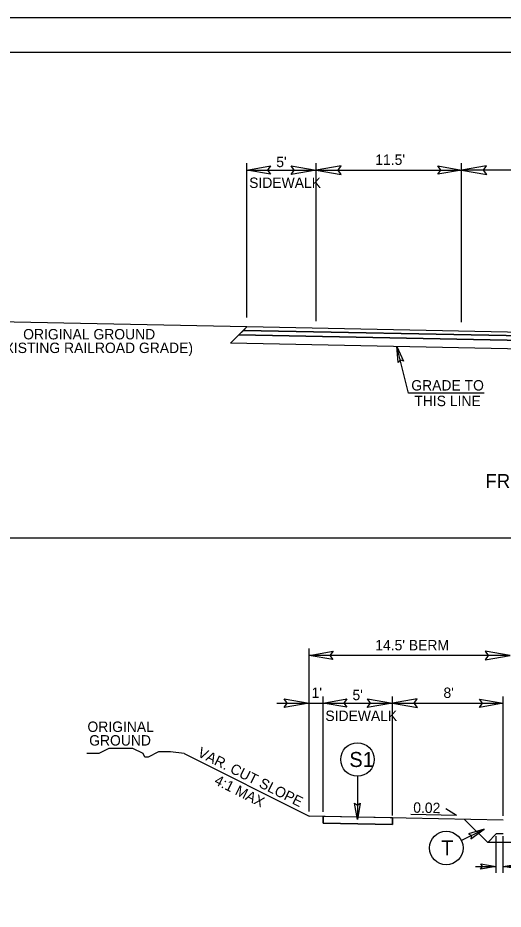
# Model space of a CAD drawing. Extents: x 1487909 to 1489267, y 497866 to 499814.
# Drawn here: x 1488926.4 to 1488961.5, y 498152.8 to 498217.1 of the extents above; entities that cross this region are included whole.
import ezdxf

# ---------------------------------------------------------------- set-up
doc = ezdxf.new("R2010")
doc.units = 0
for name, color, linetype in [('Old_Level_10', 7, 'Continuous'), ('Prop Conc 4in Sidewalk', 7, 'Continuous'), ('Prop Dimension', 7, 'Continuous'), ('Prop Dimension Text', 7, 'Continuous'), ('Prop Shade Light', 7, 'Continuous'), ('Prop Terminator CELL', 7, 'Continuous'), ('Scratch_Level_1', 7, 'Continuous'), ('Sheet Plot Border Outside CELL', 7, 'Continuous'), ('Sheet Typical CELL', 7, 'Continuous'), ('Typical Hinge Slope Arterial CELL', 7, 'Continuous'), ('Typical ID Circle CELL', 7, 'Continuous'), ('Typical Pavement Slope CELL', 7, 'Continuous'), ('Typical Pavement Slope Information CELL', 7, 'Continuous'), ('Typical Terminator CELL', 7, 'Continuous'), ('Typical Text ID Circle CELL', 7, 'Continuous')]:
    doc.layers.add(name, color=color, linetype=linetype)

msp = doc.modelspace()

# ---------------------------------------------------------------- linework, layer by layer
at = {"layer": 'Old_Level_10'}
for p, q in [((1488942.719, 498194.555), (1488942.392, 498194.228)), ((1489008.219, 498193.245), (1488942.719, 498194.555)), ((1488942.719, 498194.555), (1488942.719, 498194.555)), ((1488942.392, 498194.228), (1488987.964, 498193.317))]:
    msp.add_line(p, q, dxfattribs=at)
at = {"layer": 'Prop Conc 4in Sidewalk'}
for p, q in [((1488953.464, 498159.406), (1488948.464, 498159.506)), ((1488948.464, 498159.025), (1488948.464, 498159.506)), ((1488953.464, 498158.925), (1488948.464, 498159.025)), ((1488953.464, 498159.406), (1488953.464, 498158.925))]:
    msp.add_line(p, q, dxfattribs=at)
at = {"layer": 'Prop Dimension'}
for p, q in [((1488942.964, 498195.484), (1488942.964, 498206.612)), ((1488947.964, 498195.215), (1488947.964, 498206.612)), ((1488958.464, 498195.146), (1488958.464, 498206.612)), ((1488942.964, 498206.112), (1488947.964, 498206.112)), ((1488947.964, 498206.112), (1488958.464, 498206.112)), ((1488969.464, 498206.112), (1488958.464, 498206.112)), ((1488958.464, 498199.001), (1488958.464, 498202.36)), ((1488954.627, 498190.023), (1488953.794, 498193.387)), ((1488960.1, 498190.023), (1488954.627, 498190.023)), ((1488947.464, 498159.869), (1488947.464, 498171.612)), ((1488961.964, 498171.112), (1488947.464, 498171.112)), ((1488948.464, 498159.838), (1488948.464, 498168.153)), ((1488953.464, 498159.59), (1488953.464, 498168.153)), ((1488961.464, 498159.548), (1488961.464, 498168.153)), ((1488945.133, 498167.682), (1488947.464, 498167.682)), ((1488947.464, 498167.682), (1488948.464, 498167.682)), ((1488948.464, 498167.682), (1488953.464, 498167.682)), ((1488953.464, 498167.682), (1488961.464, 498167.682)), ((1488960.964, 498155.44), (1488960.964, 498158.094)), ((1488961.464, 498155.44), (1488961.464, 498158.094)), ((1488959.477, 498155.9), (1488960.964, 498155.9)), ((1488961.464, 498155.9), (1488964.112, 498155.9))]:
    msp.add_line(p, q, dxfattribs=at)
at = {"layer": 'Prop Shade Light'}
for p, q in [((1488942.964, 498194.8), (1488942.719, 498194.555)), ((1488942.719, 498194.555), (1489008.219, 498193.245)), ((1489007.964, 498193.5), (1488942.964, 498194.8)), ((1488953.464, 498159.406), (1488948.464, 498159.506)), ((1488948.464, 498159.506), (1488948.464, 498159.025)), ((1488948.464, 498159.025), (1488953.464, 498158.925)), ((1488953.464, 498158.925), (1488953.464, 498159.406))]:
    msp.add_line(p, q, dxfattribs=at)
at = {"layer": 'Prop Terminator CELL'}
for points in [[(1488944.674, 498205.817), (1488942.964, 498206.112), (1488944.683, 498206.416), (1488944.465, 498206.112)], [(1488946.164, 498206.422), (1488947.964, 498206.112), (1488946.154, 498205.792), (1488946.384, 498206.112)], [(1488949.764, 498206.422), (1488947.964, 498206.112), (1488949.774, 498205.792), (1488949.544, 498206.112)], [(1488956.754, 498206.406), (1488958.464, 498206.112), (1488956.744, 498205.808), (1488956.963, 498206.112)], [(1488960.264, 498206.422), (1488958.464, 498206.112), (1488960.274, 498205.792), (1488960.044, 498206.112)], [(1488953.876, 498192.248), (1488953.794, 498193.387), (1488954.26, 498192.337), (1488954.031, 498192.428)], [(1488949.174, 498170.817), (1488947.464, 498171.112), (1488949.183, 498171.416), (1488948.965, 498171.112)], [(1488960.164, 498170.802), (1488961.964, 498171.112), (1488960.154, 498171.432), (1488960.384, 498171.112)], [(1488945.664, 498167.992), (1488947.464, 498167.682), (1488945.654, 498167.362), (1488945.884, 498167.682)], [(1488950.174, 498167.387), (1488948.464, 498167.682), (1488950.183, 498167.986), (1488949.965, 498167.682)], [(1488951.664, 498167.992), (1488953.464, 498167.682), (1488951.654, 498167.362), (1488951.884, 498167.682)], [(1488955.264, 498167.992), (1488953.464, 498167.682), (1488955.274, 498167.362), (1488955.044, 498167.682)], [(1488959.754, 498167.976), (1488961.464, 498167.682), (1488959.744, 498167.378), (1488959.963, 498167.682)], [(1488959.839, 498156.094), (1488960.964, 498155.9), (1488959.833, 498155.7), (1488959.976, 498155.9)], [(1488962.589, 498155.706), (1488961.464, 498155.9), (1488962.595, 498156.1), (1488962.451, 498155.9)]]:
    msp.add_lwpolyline(points, close=True, dxfattribs=at)
at = {"layer": 'Scratch_Level_1'}
msp.add_line((1488899.964, 498179.587), (1489049.964, 498179.587), dxfattribs=at)
at = {"layer": 'Sheet Plot Border Outside CELL'}
msp.add_lwpolyline([(1489051.664, 498217.087), (1488883.264, 498217.087), (1488883.264, 498107.087), (1489051.664, 498107.087)], close=True, dxfattribs=at)
at = {"layer": 'Sheet Typical CELL'}
msp.add_lwpolyline([(1489049.964, 498214.587), (1488899.964, 498214.587), (1488899.964, 498109.587), (1489049.964, 498109.587)], close=True, dxfattribs=at)
at = {"layer": 'Typical Hinge Slope Arterial CELL'}
msp.add_line((1488938.435, 498164.041), (1488947.464, 498159.526), dxfattribs=at)
msp.add_lwpolyline([(1488938.435, 498164.041), (1488937.449, 498164.164), (1488937.203, 498164.164), (1488936.833, 498164.164), (1488936.586, 498164.164), (1488936.34, 498164.041), (1488936.094, 498163.917), (1488935.847, 498163.794), (1488935.601, 498163.794), (1488935.477, 498164.041), (1488935.231, 498164.164), (1488934.985, 498164.287), (1488934.738, 498164.41), (1488934.492, 498164.41), (1488934.245, 498164.41), (1488933.999, 498164.41), (1488933.753, 498164.41), (1488933.506, 498164.41), (1488933.26, 498164.41), (1488933.014, 498164.41), (1488932.767, 498164.287), (1488932.521, 498164.164), (1488932.275, 498164.041), (1488931.905, 498164.041), (1488931.658, 498164.041), (1488931.412, 498164.041)], dxfattribs=at)
at = {"layer": 'Typical ID Circle CELL'}
for p, q in [((1488950.949, 498162.41), (1488950.949, 498159.287)), ((1488958.439, 498157.776), (1488960.096, 498158.6))]:
    msp.add_line(p, q, dxfattribs=at)
for centre in [(1488950.949, 498163.618), (1488957.357, 498157.238)]:
    msp.add_circle(centre, 1.208, dxfattribs=at)
at = {"layer": 'Typical Pavement Slope CELL'}
for p, q in [((1488942.964, 498194.8), (1488922.63, 498195.206)), ((1488942.964, 498194.8), (1488941.791, 498193.627)), ((1489008.219, 498193.245), (1488942.719, 498194.555)), ((1489007.964, 498193.5), (1488942.964, 498194.8)), ((1489008.559, 498192.905), (1488942.392, 498194.228)), ((1489009.184, 498192.279), (1488941.791, 498193.627)), ((1488961.464, 498159.246), (1488947.464, 498159.526)), ((1488958.682, 498159.302), (1488960.351, 498157.633)), ((1488960.964, 498158.247), (1488960.351, 498157.633)), ((1488961.464, 498158.247), (1488960.964, 498158.247)), ((1488963.964, 498157.633), (1488960.351, 498157.633))]:
    msp.add_line(p, q, dxfattribs=at)
at = {"layer": 'Typical Pavement Slope Information CELL'}
for q in [(1488954.788, 498159.649), (1488957.322, 498160.056)]:
    msp.add_line((1488958.104, 498159.582), q, dxfattribs=at)
at = {"layer": 'Typical Terminator CELL'}
for points in [[(1488951.151, 498160.458), (1488950.949, 498159.287), (1488950.741, 498160.465), (1488950.949, 498160.315)], [(1488951.151, 498160.458), (1488950.949, 498159.287), (1488950.741, 498160.465), (1488950.949, 498160.315)], [(1488959.137, 498157.898), (1488960.096, 498158.6), (1488958.949, 498158.262), (1488959.175, 498158.142)]]:
    msp.add_lwpolyline(points, close=True, dxfattribs=at)

# ---------------------------------------------------------------- texts
at = {"layer": 'Prop Dimension Text'}
for s, p in [("11.5'", (1488952.236, 498206.486)), ("5'", (1488945.088, 498206.323)), ('SIDEWALK', (1488943.133, 498204.823)), ('GRADE TO', (1488954.833, 498190.218)), ('THIS LINE', (1488955.051, 498189.093)), ("14.5' BERM", (1488952.233, 498171.486)), ("1'", (1488947.638, 498168.055)), ("5'", (1488950.588, 498167.893)), ("8'", (1488957.155, 498168.055)), ('SIDEWALK', (1488948.633, 498166.393))]:
    msp.add_text(s, height=0.75, dxfattribs=at).set_placement(p)
at = {"layer": 'Typical Hinge Slope Arterial CELL'}
for s, height, p in [('ORIGINAL GROUND', 0.75, (1488926.823, 498193.904)), ('(EXISTING RAILROAD GRADE)', 0.75, (1488924.48, 498192.921)), ('FROM -L- STA. 23+57.46 TO STA. 23+83.46', 1, (1488960.183, 498183.2)), ('ORIGINAL', 0.75, (1488931.461, 498165.605)), ('GROUND', 0.75, (1488931.587, 498164.622))]:
    msp.add_text(s, height=height, dxfattribs=at).set_placement(p)
for s, p in [('VAR. CUT SLOPE', (1488939.346, 498163.875)), ('4:1 MAX', (1488940.558, 498161.872))]:
    msp.add_text(s, height=0.75, rotation=333.46576, dxfattribs=at).set_placement(p)
at = {"layer": 'Typical Pavement Slope Information CELL'}
msp.add_text('0.02', height=0.75, rotation=358.85426, dxfattribs=at).set_placement((1488954.968, 498159.784))
at = {"layer": 'Typical Text ID Circle CELL'}
for s, height, p in [('S1', 1.0817, (1488950.362, 498163.077)), ('T', 1.082, (1488956.982, 498156.697))]:
    msp.add_text(s, height=height, dxfattribs=at).set_placement(p)

doc.saveas('drawing.dxf')
